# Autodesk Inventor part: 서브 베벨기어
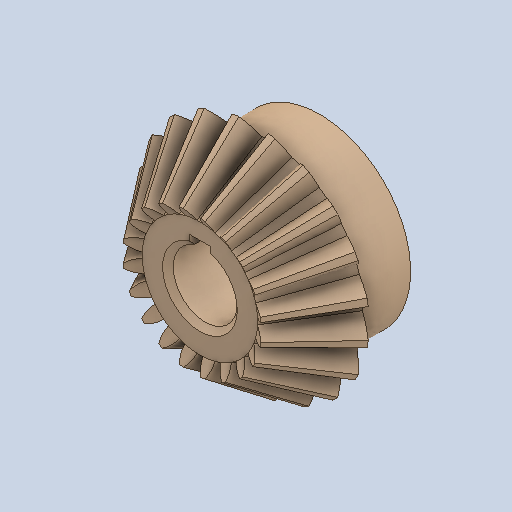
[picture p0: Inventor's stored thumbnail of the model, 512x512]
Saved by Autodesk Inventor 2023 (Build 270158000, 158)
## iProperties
Created: 2025-04
Part Number: 서브 베벨기어
Material: 강철, 탄소
Document SubType Name: Modeling
Designer: ADMIN_PC
Density: 7.87 g/cm^3
Appearance: 기본값
Author: jhkim
Revision Number: 1
Sending System: Autodesk Inventor 2026
Preprocessor: ST-DEVELOPER v20.1
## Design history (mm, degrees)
node "복구된 형상1"
  node "스케치11"
feature "Solid1"
node "스케치10"
node "솔리드1"
